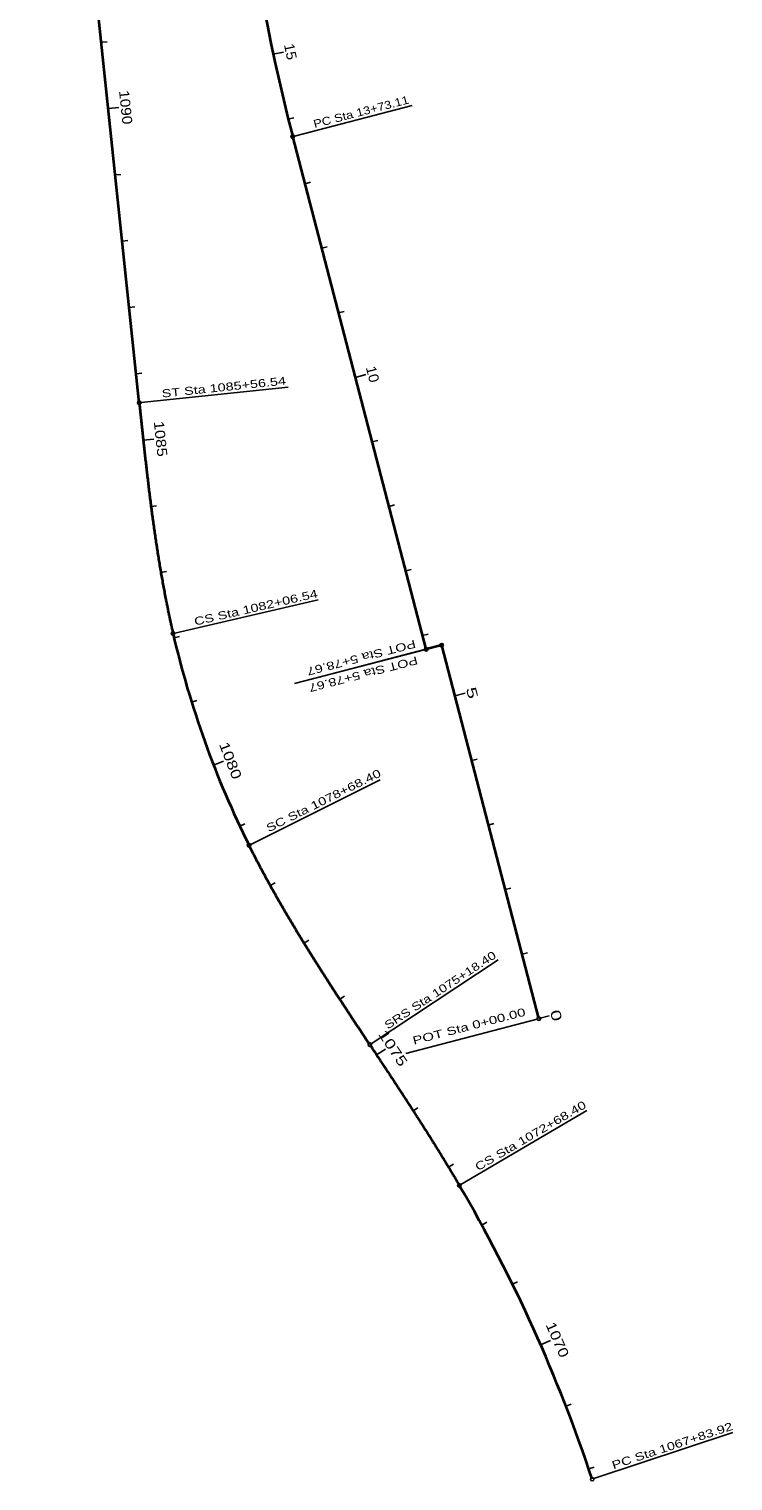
# Model space of a CAD drawing. Extents: x 771045 to 775849, y 632284 to 641017.
# Drawn here: x 772600 to 773656, y 632284 to 634461 of the extents above; entities that cross this region are included whole.
import ezdxf
from ezdxf.enums import TextEntityAlignment as Align

# ---------------------------------------------------------------- set-up
doc = ezdxf.new("R2010")
doc.units = 0
doc.header["$LTSCALE"] = 4.8
for name, color, linetype, lineweight in [('1', 7, 'Continuous', 35), ('30', 7, 'Continuous', 25), ('33', 7, 'Continuous', 25)]:
    doc.layers.add(name, color=color, linetype=linetype, lineweight=lineweight)

msp = doc.modelspace()

# ---------------------------------------------------------------- linework, layer by layer
at = {"layer": '1'}
for points in [[(772765.333, 633900.748), (772623.816, 635247.194), (772599.947, 635244.686)], [(773364.979, 632977.141), (773219.087, 633537.118), (773195.862, 633531.067), (772995.571, 634299.844)]]:
    msp.add_lwpolyline(points, dxfattribs=at)
for centre, radius, start, end in [((775767.819, 635022.104), 2864.789, 176.20056, 194.60278), ((774211.706, 633876.892), 1432.395, 193.00001, 206.52585), ((771268.778, 631567.35), 2291.831, 18.2889, 30.40085)]:
    msp.add_arc(centre, radius, start, end, dxfattribs=at)
for points in [[(772765.333, 633900.748), (772765.828, 633896.044), (772766.322, 633891.34), (772766.817, 633886.637), (772767.313, 633881.933), (772767.809, 633877.229), (772768.307, 633872.526), (772768.806, 633867.822), (772769.306, 633863.119), (772769.808, 633858.416), (772770.312, 633853.713), (772770.818, 633849.011), (772771.326, 633844.308), (772771.837, 633839.606), (772772.351, 633834.905), (772772.867, 633830.203), (772773.387, 633825.502), (772773.91, 633820.801), (772774.436, 633816.101), (772774.966, 633811.401), (772775.501, 633806.702), (772776.039, 633802.003), (772776.582, 633797.304), (772777.13, 633792.606), (772777.682, 633787.909), (772778.239, 633783.212), (772778.802, 633778.516), (772779.37, 633773.82), (772779.944, 633769.126), (772780.523, 633764.431), (772781.109, 633759.738), (772781.701, 633755.046), (772782.299, 633750.354), (772782.904, 633745.663), (772783.516, 633740.973), (772784.135, 633736.284), (772784.762, 633731.596), (772785.396, 633726.909), (772786.037, 633722.223), (772786.687, 633717.538), (772787.345, 633712.854), (772788.011, 633708.172), (772788.686, 633703.49), (772789.369, 633698.81), (772790.062, 633694.132), (772790.763, 633689.454), (772791.475, 633684.778), (772792.195, 633680.104), (772792.926, 633675.431), (772793.666, 633670.759), (772794.417, 633666.09), (772795.178, 633661.421), (772795.95, 633656.755), (772796.732, 633652.09), (772797.526, 633647.428), (772798.331, 633642.767), (772799.147, 633638.108), (772799.975, 633633.452), (772800.814, 633628.797), (772801.666, 633624.145), (772802.53, 633619.495), (772803.407, 633614.847), (772804.296, 633610.201), (772805.198, 633605.558), (772806.113, 633600.918), (772807.041, 633596.28), (772807.983, 633591.645), (772808.938, 633587.013), (772809.907, 633582.384), (772810.89, 633577.757), (772811.888, 633573.134), (772812.9, 633568.514), (772813.926, 633563.897), (772814.968, 633559.283), (772816.024, 633554.673)], [(773111.247, 632937.98), (773108.635, 632941.923), (773106.023, 632945.866), (773103.411, 632949.81), (773100.8, 632953.753), (773098.189, 632957.697), (773095.58, 632961.642), (773092.971, 632965.587), (773090.364, 632969.533), (773087.758, 632973.48), (773085.154, 632977.429), (773082.551, 632981.378), (773079.95, 632985.328), (773077.352, 632989.28), (773074.756, 632993.234), (773072.162, 632997.189), (773069.571, 633001.146), (773066.982, 633005.105), (773064.397, 633009.065), (773061.815, 633013.028), (773059.236, 633016.993), (773056.661, 633020.96), (773054.09, 633024.93), (773051.522, 633028.902), (773048.959, 633032.877), (773046.399, 633036.854), (773043.845, 633040.834), (773041.294, 633044.818), (773038.749, 633048.804), (773036.209, 633052.794), (773033.673, 633056.787), (773031.143, 633060.783), (773028.619, 633064.782), (773026.1, 633068.786), (773023.588, 633072.793), (773021.081, 633076.804), (773018.581, 633080.818), (773016.087, 633084.837), (773013.599, 633088.86), (773011.119, 633092.887), (773008.645, 633096.919), (773006.179, 633100.954), (773003.72, 633104.995), (773001.269, 633109.04), (772998.825, 633113.089), (772996.39, 633117.144), (772993.962, 633121.203), (772991.543, 633125.267), (772989.133, 633129.337), (772986.731, 633133.411), (772984.338, 633137.491), (772981.954, 633141.576), (772979.579, 633145.666), (772977.214, 633149.762), (772974.859, 633153.864), (772972.514, 633157.971), (772970.178, 633162.084), (772967.853, 633166.203), (772965.539, 633170.328), (772963.235, 633174.458), (772960.942, 633178.595), (772958.66, 633182.738), (772956.389, 633186.887), (772954.13, 633191.042), (772951.882, 633195.204), (772949.647, 633199.372), (772947.423, 633203.546), (772945.212, 633207.727), (772943.013, 633211.915), (772940.827, 633216.109), (772938.654, 633220.31), (772936.494, 633224.518), (772934.348, 633228.732), (772932.215, 633232.954), (772930.096, 633237.182)], [(773111.247, 632937.98), (773113.113, 632935.164), (773114.979, 632932.348), (773116.845, 632929.531), (773118.71, 632926.715), (773120.576, 632923.898), (773122.441, 632921.081), (773124.305, 632918.264), (773126.17, 632915.447), (773128.034, 632912.629), (773129.897, 632909.811), (773131.76, 632906.992), (773133.622, 632904.174), (773135.484, 632901.355), (773137.344, 632898.535), (773139.204, 632895.715), (773141.064, 632892.894), (773142.922, 632890.072), (773144.779, 632887.25), (773146.636, 632884.428), (773148.491, 632881.604), (773150.345, 632878.78), (773152.198, 632875.955), (773154.05, 632873.13), (773155.9, 632870.303), (773157.749, 632867.475), (773159.597, 632864.647), (773161.443, 632861.818), (773163.287, 632858.988), (773165.131, 632856.156), (773166.972, 632853.324), (773168.812, 632850.49), (773170.65, 632847.655), (773172.486, 632844.82), (773174.32, 632841.983), (773176.153, 632839.144), (773177.983, 632836.305), (773179.811, 632833.464), (773181.638, 632830.622), (773183.462, 632827.778), (773185.284, 632824.933), (773187.103, 632822.087), (773188.921, 632819.239), (773190.736, 632816.389), (773192.548, 632813.538), (773194.358, 632810.686), (773196.166, 632807.832), (773197.971, 632804.976), (773199.773, 632802.118), (773201.572, 632799.259), (773203.369, 632796.398), (773205.163, 632793.535), (773206.953, 632790.67), (773208.741, 632787.804), (773210.526, 632784.936), (773212.308, 632782.065), (773214.087, 632779.193), (773215.862, 632776.319), (773217.634, 632773.443), (773219.403, 632770.564), (773221.169, 632767.684), (773222.931, 632764.801), (773224.689, 632761.917), (773226.444, 632759.03), (773228.196, 632756.141), (773229.943, 632753.25), (773231.687, 632750.356), (773233.427, 632747.461), (773235.163, 632744.562), (773236.896, 632741.662), (773238.624, 632738.759), (773240.348, 632735.854), (773242.068, 632732.946), (773243.784, 632730.036), (773245.496, 632727.123)]]:
    msp.add_spline(points, degree=3, dxfattribs=at)
at = {"layer": '30'}
for p, q in [((772708.526, 634441.227), (772716.98, 634442.116)), ((772966.31, 634423.304), (772981.956, 634426.648)), ((772718.979, 634341.775), (772734.892, 634343.447)), ((772988.914, 634325.897), (772997.159, 634327.963)), ((772729.432, 634242.323), (772737.886, 634243.211)), ((773014.003, 634229.096), (773022.229, 634231.239)), ((772739.885, 634142.87), (772748.338, 634143.759)), ((773039.215, 634132.326), (773047.44, 634134.469)), ((772750.338, 634043.418), (772758.791, 634044.307)), ((773064.427, 634035.556), (773072.652, 634037.699)), ((772760.791, 633943.966), (772769.244, 633944.855)), ((773089.638, 633938.787), (773105.121, 633942.821)), ((772771.303, 633844.52), (772787.21, 633846.243)), ((773114.85, 633842.017), (773123.075, 633844.16)), ((772782.964, 633745.204), (772791.393, 633746.299)), ((773140.062, 633745.247), (773148.287, 633747.39)), ((772797.718, 633646.306), (772806.095, 633647.747)), ((773165.273, 633648.478), (773173.499, 633650.621)), ((772817.51, 633548.3), (772825.784, 633550.25)), ((773190.485, 633551.708), (773198.71, 633553.851)), ((772843.828, 633451.846), (772851.945, 633454.369)), ((773238.921, 633460.989), (773254.404, 633465.023)), ((772876.81, 633357.463), (772891.721, 633363.265)), ((773264.133, 633364.219), (773272.358, 633366.362)), ((772916.295, 633265.611), (772923.982, 633269.238)), ((773289.344, 633267.45), (773297.57, 633269.593)), ((772961.998, 633176.686), (772969.433, 633180.806)), ((773314.556, 633170.68), (773322.781, 633172.823)), ((773012.616, 633090.454), (773019.853, 633094.913)), ((773339.768, 633073.91), (773347.993, 633076.053)), ((773066.328, 633006.107), (773073.445, 633010.754)), ((773364.979, 632977.141), (773380.462, 632981.174)), ((773121.407, 632922.642), (773134.748, 632931.475)), ((773176.236, 632839.015), (773183.379, 632843.622)), ((773229.324, 632754.274), (773236.6, 632758.67)), ((773279.223, 632667.622), (773286.68, 632671.703)), ((773325.303, 632578.881), (773332.93, 632582.632)), ((773367.468, 632488.213), (773382.12, 632494.642)), ((773405.638, 632395.794), (773413.563, 632398.866)), ((773439.74, 632301.796), (773447.792, 632304.52))]:
    msp.add_line(p, q, dxfattribs=at)
at = {"layer": '33'}
for p, q in [((772998.184, 634300.525), (773175.036, 634346.601)), ((772768.018, 633901.03), (772988.771, 633924.232)), ((772818.655, 633555.28), (773033.783, 633604.946)), ((773216.474, 633536.437), (773021.564, 633485.657)), ((773216.474, 633536.437), (773130.258, 633513.975)), ((773193.25, 633530.386), (772998.339, 633479.606)), ((772932.511, 633238.388), (773126.675, 633335.304)), ((773113.498, 632939.472), (773303.659, 633065.46)), ((773362.367, 632976.46), (773165.17, 632925.084)), ((773247.825, 632728.49), (773436.829, 632839.382)), ((773447.404, 632287.394), (773656.141, 632356.382))]:
    msp.add_line(p, q, dxfattribs=at)
for centre in [(772995.571, 634299.844), (772765.333, 633900.748), (772816.024, 633554.673), (773219.087, 633537.118), (773219.087, 633537.118), (773195.862, 633531.067), (772930.096, 633237.182), (773364.979, 632977.141), (773111.247, 632937.981), (773245.496, 632727.124), (773444.84, 632286.547)]:
    msp.add_circle(centre, 2.7, dxfattribs=at)

# ---------------------------------------------------------------- texts
at = {"layer": '30'}
for s, rotation, width, p in [('15', 282.065, 1.1, (772984.932, 634425.645)), ('1090', 276, 1.15, (772737.659, 634342.946)), ('10', 284.603, 1.1, (773108.227, 633941.61)), ('1085', 276.183, 1.2, (772789.982, 633845.727)), ('5', 284.603, 1.55, (773257.51, 633463.813)), ('1080', 291.262, 1.3, (772895.295, 633361.525)), ('0', 284.603, 1.5, (773383.568, 632979.964)), ('1075', 303.509, 1.35, (773139.74, 632928.826)), ('1070', 293.691, 1.25, (773385.914, 632492.714))]:
    msp.add_text(s, height=15, rotation=rotation, dxfattribs=dict(at, width=width)).set_placement(p, align=Align.CENTER)
at = {"layer": '33'}
for s, rotation, width, p in [('PC Sta 13+73.11', 14.603, 1.2, (773028.432, 634312.539)), ('ST Sta 1085+56.54', 6, 1.35, (772799.723, 633908.384)), ('CS Sta 1082+06.54', 13, 1.35, (772849.227, 633566.443)), ('POT Sta 5+78.67', 194.603, 1.35, (773178.324, 633545.393)), ('POT Sta 5+78.67', 194.603, 1.35, (773181.286, 633520.673)), ('SC Sta 1078+68.40', 26.526, 1.35, (772959.625, 633256.392)), ('SRS Sta 1075+18.40', 33.526, 1.3, (773138.215, 632960.646)), ('POT Sta 0+00.00', 14.603, 1.4, (773177.355, 632937.963)), ('CS Sta 1072+68.40', 30.401, 1.35, (773273.66, 632748.285)), ('PC Sta 1067+83.92', 18.289, 1.35, (773476.817, 632301.328))]:
    msp.add_text(s, height=12, rotation=rotation, dxfattribs=dict(at, width=width)).set_placement(p)

doc.saveas('drawing.dxf')
